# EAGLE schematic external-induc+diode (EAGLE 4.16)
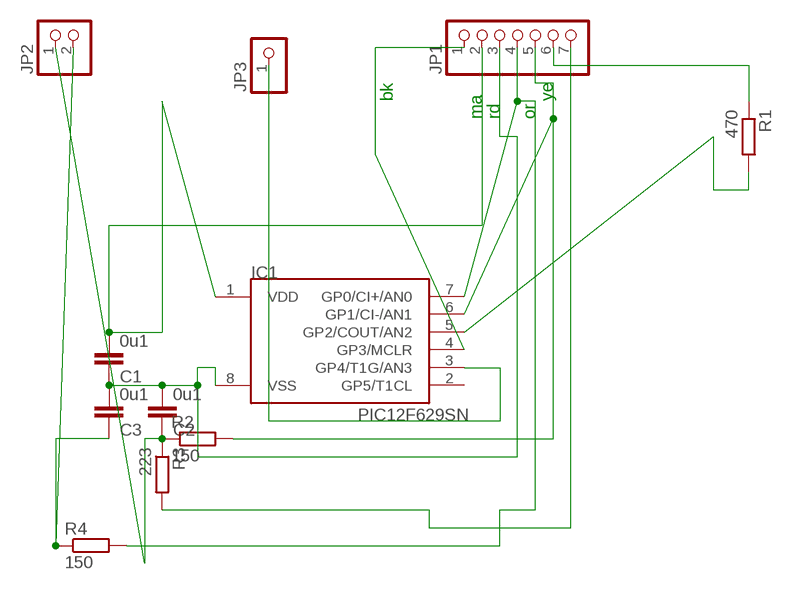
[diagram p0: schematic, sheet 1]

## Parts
C1  0u1  C-EUC1206  [C1206]
C2  0u1  C-EUC1206  [C1206]
C3  0u1  C-EUC1206  [C1206]
IC1  PIC12F629SN  [SO-08]
JP1  PINHD-1X7  [1X07]
JP2  PINHD-1X2  [1X02]
JP3  PINHD-1X1  [1X01]
R1  470  R-EU_R1206  [R1206]
R2  150  R-EU_R1206  [R1206]
R3  223  R-EU_R1206  [R1206]
R4  150  R-EU_R1206  [R1206]

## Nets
N$1: C1.1 C2.2 C3.2 IC1.8(VSS) JP1.3
N$2: IC1.7(GP0/CI+/AN0) JP1.4 R4.2
N$3: JP1.6 R1.1
N$4: IC1.6(GP1/CI-/AN1) JP1.5 R2.2
N$5: JP1.7 R3.2
N$6: C1.2 IC1.1(VDD) JP1.2
N$7: C2.1 JP2.1 R2.1 R3.1
N$9: IC1.3(GP4/T1G/AN3) JP3.1
N$11: C3.1 JP2.2 R4.1
N$12: IC1.4(GP3/MCLR) JP1.1
N$14: IC1.5(GP2/COUT/AN2) R1.2
Unconnected: IC1.2(GP5/T1CL)

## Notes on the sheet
- bk | ye
- ma | rd | or

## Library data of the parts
C1-C3 = rcl:C-EU: CAPACITOR, European symbol
IC1 = microchip-3:PIC12F6*: uPC nW 1k Program Flash memory 2x Timer Comparator 10b A/D converter/ 4xIN
JP1 = pinhead(2):PINHD-1X7: PIN HEADER
JP2 = pinhead(2):PINHD-1X2: PIN HEADER
JP3 = pinhead(2):PINHD-1X1: PIN HEADER
R1-R4 = rcl:R-EU_: RESISTOR, European symbol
